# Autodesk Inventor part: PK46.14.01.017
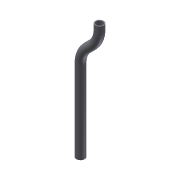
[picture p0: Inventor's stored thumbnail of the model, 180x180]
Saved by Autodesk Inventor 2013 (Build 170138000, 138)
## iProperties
Created: 2005-03
Part Number: PK46.14.01.017
Document SubType Name: Modeling
Designer: elarisa
Manufacturer: Standard
Standards Organization: Custom
Material: Steel
Mass: 411.783 g
Surface Area: 422.714 cm^2
Volume: 52.4564 cm^3
Density: 7.85 g/cm^3
Author: elarisa
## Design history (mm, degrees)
sketch "Эскиз1"
  geometry: C1 r 11 at (-14.175, -0.194); C2 r 8.5 at (-14.175, -0.194)
  constraints: 2 centre point, 1 coincident
  dimensions: "d0" = 22 diameter of C1; "d1" = 17 diameter of C2
sketch "Эскиз2"
  geometry: L1 (25.175, 0)-(3.175, 0) reference; L2 (14.175, 0)-(14.175, 214.733); L3 (-3.692, 257.866)-(-17.959, 272.134); L4 (-35.825, 315.267)-(-35.825, 330); A1 r 61 centre (25.175, 315.267) between (-35.825, 315.267) and (-17.959, 272.134); A2 r 61 centre (-46.825, 214.733) between (14.175, 214.733) and (-3.692, 257.866); 2 further points
  constraints: 6 end point, 4 point on circle, 4 point on line, 4 tangent, 2 centre point, 1 equal radius
  dimensions: "d3" = 240 distance of point (14.175, 240) L2.start; "d4" = 0 horizontal distance of point (14.175, 240) L2.start; "d8" = 50 horizontal distance of point (-35.825, 290) point (14.175, 240); "d9" = 50 horizontal distance of point (-35.825, 290) point (14.175, 240) (derived); "d10" = 0 horizontal distance of L4.end point (-35.825, 290); "d11" = 40 distance of point (-35.825, 290) L4.end; "d14" = 61 radius of A1; "d16" = 330 vertical distance of L2.start L4.end
feature "Сдвиг2" sketch "Эскиз1", "Эскиз2" dims "d15" = 0
body "Solid1"
